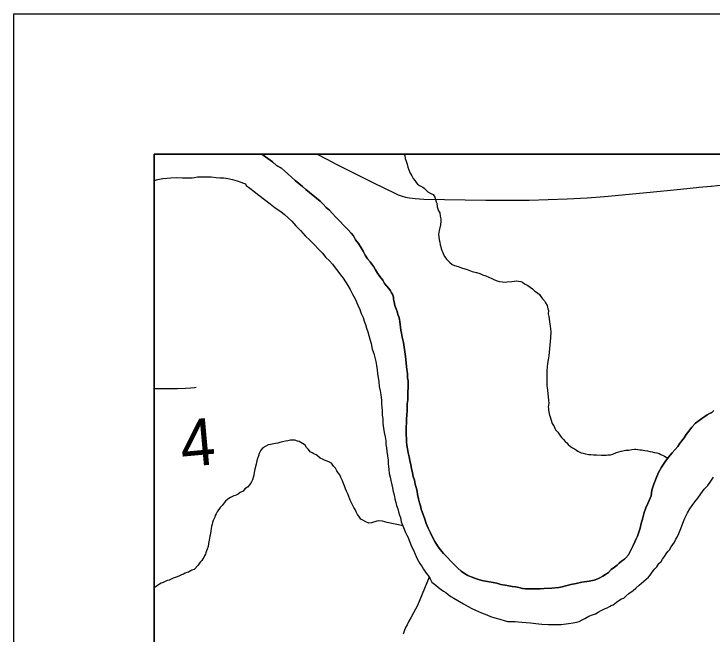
# Model space of a CAD drawing. Extents: x -483 to 680, y 0 to 440.
# Drawn here: x 37.11 to 79.41, y 366.86 to 404.45 of the extents above; entities that cross this region are included whole.
import ezdxf

# ---------------------------------------------------------------- set-up
doc = ezdxf.new("R2010")
doc.units = 0
for name, color, linetype in [('GM_X_Major_River', 7, 'Continuous'), ('GM_X_Minor_River', 7, 'Continuous'), ('GM_X_Township_Road', 7, 'Continuous'), ('GM_X_Township_Road_Text', 7, 'Continuous'), ('SH_Cut_Line', 7, 'Continuous'), ('SH_Text', 7, 'Continuous')]:
    doc.layers.add(name, color=color, linetype=linetype)

msp = doc.modelspace()

# ---------------------------------------------------------------- linework, layer by layer
at = {"layer": 'GM_X_Major_River'}
for points in [[(60.949, 382.647), (60.918, 382.895), (60.823, 383.676), (60.792, 383.962), (60.742, 384.248), (60.712, 384.534), (60.625, 384.859), (60.593, 385.106), (60.559, 385.278), (60.526, 385.469), (60.511, 385.64), (60.496, 385.792), (60.462, 385.945), (60.428, 386.098), (60.374, 386.232), (60.322, 386.404), (60.269, 386.577), (60.179, 386.769), (60.147, 386.998), (60.113, 387.169), (60.097, 387.284), (60.044, 387.456), (59.989, 387.552), (59.916, 387.668), (59.825, 387.803), (59.695, 387.94), (59.567, 388.114), (59.457, 388.306), (59.273, 388.539), (59.145, 388.732), (59.018, 388.944), (58.908, 389.118), (58.798, 389.273), (58.688, 389.427), (58.54, 389.602), (58.394, 389.834), (58.267, 390.065), (58.139, 390.277), (57.975, 390.528), (57.809, 390.76), (57.683, 391.01), (57.535, 391.166), (57.331, 391.38), (57.09, 391.633), (56.85, 391.886), (56.609, 392.139), (56.387, 392.372), (56.221, 392.566), (56.035, 392.723), (55.85, 392.917), (55.665, 393.093), (55.013, 393.622), (54.79, 393.799), (54.586, 393.994), (54.362, 394.171), (54.138, 394.347), (53.916, 394.562), (53.712, 394.757), (53.507, 394.933), (53.322, 395.109), (53.022, 395.268), (52.78, 395.483), (52.481, 395.681), (52.202, 395.897), (52.129, 395.95)], [(52.129, 395.95), (52.202, 395.897), (52.481, 395.681), (52.78, 395.483), (53.022, 395.268), (53.322, 395.109), (53.507, 394.933), (53.712, 394.757), (53.916, 394.562), (54.138, 394.347), (54.362, 394.171), (54.586, 393.994), (54.79, 393.799), (55.013, 393.622), (55.665, 393.093), (55.85, 392.917), (56.035, 392.723), (56.221, 392.566), (56.387, 392.372), (56.609, 392.139), (56.85, 391.886), (57.09, 391.633), (57.331, 391.38), (57.535, 391.166), (57.683, 391.01), (57.809, 390.76), (57.975, 390.528), (58.139, 390.277), (58.267, 390.065), (58.394, 389.834), (58.54, 389.602), (58.688, 389.427), (58.798, 389.273), (58.908, 389.118), (59.018, 388.944), (59.145, 388.732), (59.273, 388.539), (59.457, 388.306), (59.567, 388.114), (59.695, 387.94), (59.825, 387.803), (59.916, 387.668), (59.989, 387.552), (60.044, 387.456), (60.097, 387.284), (60.113, 387.169), (60.147, 386.998), (60.179, 386.769), (60.269, 386.577), (60.322, 386.404), (60.374, 386.232), (60.428, 386.098), (60.462, 385.945), (60.496, 385.792), (60.511, 385.64), (60.526, 385.469), (60.559, 385.278), (60.593, 385.106), (60.625, 384.859), (60.712, 384.534), (60.742, 384.248), (60.792, 383.962), (60.823, 383.676), (60.918, 382.895), (60.949, 382.647)], [(45.608, 394.363), (45.821, 394.406), (46.126, 394.475), (46.621, 394.519), (46.983, 394.529), (47.324, 394.52)], [(45.608, 394.363), (45.821, 394.406), (46.126, 394.475), (46.621, 394.519), (46.983, 394.529), (47.324, 394.52)], [(47.324, 394.52), (47.571, 394.514), (47.742, 394.51), (47.913, 394.524), (48.046, 394.54), (48.237, 394.573), (48.503, 394.585), (48.807, 394.578), (49.054, 394.571), (49.357, 394.545), (49.603, 394.519), (49.831, 394.513), (50.077, 394.469), (50.36, 394.405), (50.625, 394.342), (50.85, 394.26), (51.02, 394.199), (51.133, 394.158), (51.187, 394.042), (51.392, 393.885), (51.653, 393.689), (51.951, 393.472), (52.286, 393.198), (52.641, 392.942), (52.939, 392.707), (53.275, 392.47), (53.498, 392.294), (53.721, 392.098), (53.944, 391.883), (54.184, 391.612), (54.462, 391.32), (54.758, 391.008), (55.054, 390.716), (55.795, 389.957), (55.997, 389.686), (56.22, 389.49), (56.405, 389.276), (56.57, 389.063), (56.736, 388.85), (56.902, 388.637), (57.048, 388.425), (57.195, 388.212), (57.341, 387.98), (57.487, 387.749), (57.613, 387.461), (57.777, 387.172), (57.938, 386.807), (58.065, 386.538), (58.153, 386.289), (58.262, 386.058), (58.332, 385.828), (58.402, 385.618), (58.473, 385.407), (58.543, 385.177), (58.614, 384.967), (58.665, 384.737), (58.754, 384.469), (58.821, 384.126), (58.91, 383.877), (58.979, 383.628), (59.03, 383.38), (59.081, 383.132), (59.113, 382.884), (59.145, 382.636), (59.177, 382.408), (59.208, 382.141), (59.24, 381.874), (59.29, 381.607), (59.341, 381.359), (59.37, 381.035), (59.384, 380.826), (59.398, 380.617), (59.411, 380.389), (59.424, 380.142), (59.456, 379.894), (59.468, 379.628), (59.499, 379.342), (59.549, 379.075), (59.6, 378.808), (59.632, 378.579), (59.645, 378.351), (59.678, 378.141), (59.692, 377.932), (59.773, 377.398), (59.787, 377.189), (59.802, 377.018), (59.816, 376.827), (59.848, 376.599), (59.9, 376.369), (59.952, 376.178), (60.002, 375.911), (60.054, 375.72), (60.087, 375.51), (60.139, 375.3), (60.19, 375.052), (60.241, 374.842), (60.293, 374.65), (60.365, 374.459), (60.417, 374.267), (60.469, 374.076), (60.522, 373.923)], [(47.324, 394.52), (47.571, 394.514), (47.742, 394.51), (47.913, 394.524), (48.046, 394.54), (48.237, 394.573), (48.503, 394.585), (48.807, 394.578), (49.054, 394.571), (49.357, 394.545), (49.603, 394.519), (49.831, 394.513), (50.077, 394.469), (50.36, 394.405), (50.625, 394.342), (50.85, 394.26), (51.02, 394.199), (51.133, 394.158), (51.187, 394.042), (51.392, 393.885), (51.653, 393.689), (51.951, 393.472), (52.286, 393.198), (52.641, 392.942), (52.939, 392.707), (53.275, 392.47), (53.498, 392.294), (53.721, 392.098), (53.944, 391.883), (54.184, 391.612), (54.462, 391.32), (54.758, 391.008), (55.054, 390.716), (55.795, 389.957), (55.997, 389.686), (56.22, 389.49), (56.405, 389.276), (56.57, 389.063), (56.736, 388.85), (56.902, 388.637), (57.048, 388.425), (57.195, 388.212), (57.341, 387.98), (57.487, 387.749), (57.613, 387.461), (57.777, 387.172), (57.938, 386.807), (58.065, 386.538), (58.153, 386.289), (58.262, 386.058), (58.332, 385.828), (58.402, 385.618), (58.473, 385.407), (58.543, 385.177), (58.614, 384.967), (58.665, 384.737), (58.754, 384.469), (58.821, 384.126), (58.91, 383.877), (58.979, 383.628), (59.03, 383.38), (59.081, 383.132), (59.113, 382.884), (59.145, 382.636), (59.177, 382.408), (59.208, 382.141), (59.24, 381.874), (59.29, 381.607), (59.341, 381.359), (59.37, 381.035), (59.384, 380.826), (59.398, 380.617), (59.411, 380.389), (59.424, 380.142), (59.456, 379.894), (59.468, 379.628), (59.499, 379.342), (59.549, 379.075), (59.6, 378.808), (59.632, 378.579), (59.645, 378.351), (59.678, 378.141), (59.692, 377.932), (59.773, 377.398), (59.787, 377.189), (59.802, 377.018), (59.816, 376.827), (59.848, 376.599), (59.9, 376.369), (59.952, 376.178), (60.002, 375.911), (60.054, 375.72), (60.087, 375.51), (60.139, 375.3), (60.19, 375.052), (60.241, 374.842), (60.293, 374.65), (60.365, 374.459), (60.417, 374.267), (60.469, 374.076), (60.522, 373.923)], [(74.973, 373.043), (74.891, 372.798), (74.811, 372.629), (74.73, 372.442), (74.63, 372.235), (74.55, 372.066), (74.35, 371.673), (74.193, 371.487), (74.096, 371.394), (73.922, 371.285), (73.786, 371.155), (73.651, 371.045), (73.495, 370.916), (73.302, 370.769), (73.127, 370.602), (72.952, 370.474), (72.798, 370.364), (72.644, 370.292), (72.49, 370.201), (72.26, 370.131), (71.955, 370.062), (71.516, 369.998), (71.173, 369.93), (70.848, 369.863), (70.332, 369.724), (70.122, 369.691), (69.703, 369.645), (69.227, 369.619), (68.999, 369.606), (68.714, 369.594), (68.505, 369.599), (68.296, 369.605), (68.107, 369.609), (67.917, 369.633), (67.709, 369.676), (67.502, 369.72), (67.293, 369.744), (67.085, 369.787), (66.878, 369.831), (66.613, 369.875), (66.367, 369.938), (66.027, 370.004), (65.8, 370.048), (65.555, 370.092), (65.309, 370.155), (65.064, 370.237), (64.82, 370.339), (64.613, 370.42), (64.407, 370.539), (64.202, 370.677), (63.997, 370.853), (63.793, 371.048), (63.127, 371.749), (62.943, 371.981), (62.778, 372.213), (62.613, 372.465), (62.468, 372.734), (62.342, 373.003), (62.215, 373.272), (62.09, 373.56), (62.001, 373.828), (61.931, 374.039), (61.841, 374.269), (61.789, 374.441), (61.736, 374.633), (61.684, 374.824), (61.614, 375.054), (61.564, 375.321), (61.531, 375.53), (61.479, 375.741), (61.428, 375.951), (61.376, 376.18), (61.306, 376.41), (61.255, 376.639), (61.205, 376.906), (61.153, 377.116), (61.102, 377.383), (61.051, 377.613), (61, 377.842), (60.949, 378.09), (60.917, 378.319), (60.903, 378.509), (60.889, 378.718), (60.875, 378.927), (60.88, 379.117), (60.869, 379.421), (60.894, 379.667), (60.899, 379.895), (60.906, 380.142), (60.931, 380.388), (60.936, 380.616), (60.942, 380.825), (60.966, 381.052), (60.971, 381.223), (60.975, 381.413), (60.98, 381.583), (61.003, 381.773), (60.99, 382.001), (60.995, 382.21), (60.962, 382.4), (60.949, 382.647)], [(60.949, 382.647), (60.962, 382.4), (60.995, 382.21), (60.99, 382.001), (61.003, 381.773), (60.98, 381.583), (60.975, 381.413), (60.971, 381.223), (60.966, 381.052), (60.942, 380.825), (60.936, 380.616), (60.931, 380.388), (60.906, 380.142), (60.899, 379.895), (60.894, 379.667), (60.869, 379.421), (60.88, 379.117), (60.875, 378.927), (60.889, 378.718), (60.903, 378.509), (60.917, 378.319), (60.949, 378.09), (61, 377.842), (61.051, 377.613), (61.102, 377.383), (61.153, 377.116), (61.205, 376.906), (61.255, 376.639), (61.306, 376.41), (61.376, 376.18), (61.428, 375.951), (61.479, 375.741), (61.531, 375.53), (61.564, 375.321), (61.614, 375.054), (61.684, 374.824), (61.736, 374.633), (61.789, 374.441), (61.841, 374.269), (61.931, 374.039), (62.001, 373.828), (62.09, 373.56), (62.215, 373.272), (62.342, 373.003), (62.468, 372.734), (62.613, 372.465), (62.778, 372.213), (62.943, 371.981), (63.127, 371.749), (63.793, 371.048), (63.997, 370.853), (64.202, 370.677), (64.407, 370.539), (64.613, 370.42), (64.82, 370.339), (65.064, 370.237), (65.309, 370.155), (65.555, 370.092), (65.8, 370.048), (66.027, 370.004), (66.367, 369.938), (66.613, 369.875), (66.878, 369.831), (67.085, 369.787), (67.293, 369.744), (67.502, 369.72), (67.709, 369.676), (67.917, 369.633), (68.107, 369.609), (68.296, 369.605), (68.505, 369.599), (68.714, 369.594), (68.999, 369.606), (69.227, 369.619), (69.703, 369.645), (70.122, 369.691), (70.332, 369.724), (70.848, 369.863), (71.173, 369.93), (71.516, 369.998), (71.955, 370.062), (72.26, 370.131), (72.49, 370.201), (72.644, 370.292), (72.798, 370.364), (72.952, 370.474), (73.127, 370.602), (73.302, 370.769), (73.495, 370.916), (73.651, 371.045), (73.786, 371.155), (73.922, 371.285), (74.096, 371.394), (74.193, 371.487), (74.35, 371.673), (74.55, 372.066), (74.63, 372.235), (74.73, 372.442), (74.811, 372.629), (74.891, 372.798), (74.973, 373.043)], [(79.507, 380.41), (79.39, 380.299), (79.255, 380.226), (79.102, 380.154), (78.966, 380.044), (78.792, 379.934), (78.618, 379.806), (78.405, 379.64), (78.19, 379.399), (77.994, 379.157), (77.837, 378.952), (77.718, 378.765), (77.561, 378.56), (77.443, 378.392), (77.325, 378.224), (77.168, 378.039), (76.993, 377.853), (76.777, 377.593), (76.541, 377.276), (76.344, 376.977), (76.165, 376.659), (76.024, 376.321), (75.881, 375.944), (75.758, 375.587), (75.712, 375.246), (75.651, 375.096), (75.591, 374.964), (75.51, 374.776), (75.39, 374.514), (75.288, 374.231), (75.204, 373.911), (75.119, 373.571), (75.055, 373.288), (74.973, 373.043)], [(74.973, 373.043), (75.055, 373.288), (75.119, 373.571), (75.204, 373.911), (75.288, 374.231), (75.39, 374.514), (75.51, 374.776), (75.591, 374.964), (75.651, 375.096), (75.712, 375.246), (75.758, 375.587), (75.881, 375.944), (76.024, 376.321), (76.165, 376.659), (76.344, 376.977), (76.541, 377.276), (76.777, 377.593), (76.993, 377.853), (77.168, 378.039), (77.325, 378.224), (77.443, 378.392), (77.561, 378.56), (77.718, 378.765), (77.837, 378.952), (77.994, 379.157), (78.19, 379.399), (78.405, 379.64), (78.618, 379.806), (78.792, 379.934), (78.966, 380.044), (79.102, 380.154), (79.255, 380.226), (79.39, 380.299), (79.507, 380.41)], [(77.646, 373.583), (77.767, 373.884), (77.927, 374.202), (78.066, 374.446), (78.204, 374.651), (78.362, 374.875), (78.538, 375.098), (78.735, 375.359), (78.932, 375.639), (79.146, 375.861), (79.324, 376.123), (79.501, 376.365)], [(77.646, 373.583), (77.767, 373.884), (77.927, 374.202), (78.066, 374.446), (78.204, 374.651), (78.362, 374.875), (78.538, 375.098), (78.735, 375.359), (78.932, 375.639), (79.146, 375.861), (79.324, 376.123), (79.501, 376.365)], [(60.522, 373.923), (60.572, 373.656), (60.681, 373.425), (60.751, 373.214), (60.842, 373.022), (60.913, 372.85), (60.986, 372.715), (61.04, 372.599), (61.111, 372.389), (61.2, 372.159), (61.308, 371.947), (61.416, 371.697), (61.542, 371.428), (61.706, 371.139), (61.834, 370.946), (61.925, 370.792), (61.998, 370.676), (62.09, 370.56), (62.201, 370.405), (62.329, 370.212), (62.437, 370), (62.661, 369.824), (62.828, 369.687), (62.996, 369.568), (63.127, 369.47), (63.276, 369.371), (63.425, 369.254), (63.574, 369.136), (63.762, 369.036), (64.342, 368.699), (64.623, 368.54), (64.848, 368.42), (65.073, 368.319), (65.261, 368.238), (65.43, 368.158), (65.6, 368.097), (65.769, 368.017), (65.976, 367.935), (66.239, 367.853), (66.541, 367.769), (66.805, 367.686), (67.012, 367.624), (67.259, 367.618), (67.468, 367.613), (67.658, 367.608), (67.885, 367.583), (68.15, 367.557), (68.416, 367.532), (68.738, 367.504), (69.097, 367.457), (69.496, 367.447), (69.876, 367.438), (70.256, 367.447), (70.713, 367.492), (70.999, 367.542), (71.19, 367.575), (71.362, 367.628), (71.535, 367.718), (71.708, 367.809), (71.939, 367.936), (72.17, 368.025), (72.342, 368.097), (72.497, 368.188), (72.689, 368.297), (72.881, 368.387), (73.054, 368.458), (73.189, 368.531), (73.304, 368.585), (73.419, 368.639), (73.516, 368.712), (73.613, 368.786), (73.749, 368.896), (73.922, 368.987), (74.056, 369.04), (74.192, 369.151), (74.367, 369.317), (74.619, 369.501), (74.793, 369.648), (74.988, 369.833), (75.551, 370.313), (75.648, 370.424), (75.747, 370.555), (75.845, 370.685), (75.943, 370.816), (76.06, 370.945), (76.179, 371.132), (76.315, 371.262), (76.414, 371.411), (76.531, 371.56), (76.631, 371.729), (76.729, 371.859), (76.827, 371.97), (76.926, 372.139), (77.025, 372.288), (77.123, 372.438), (77.222, 372.606), (77.302, 372.737), (77.402, 372.962), (77.483, 373.169), (77.564, 373.357), (77.646, 373.583)], [(60.522, 373.923), (60.572, 373.656), (60.681, 373.425), (60.751, 373.214), (60.842, 373.022), (60.913, 372.85), (60.986, 372.715), (61.04, 372.599), (61.111, 372.389), (61.2, 372.159), (61.308, 371.947), (61.416, 371.697), (61.542, 371.428), (61.706, 371.139), (61.834, 370.946), (61.925, 370.792), (61.998, 370.676), (62.09, 370.56), (62.201, 370.405), (62.329, 370.212), (62.437, 370), (62.661, 369.824), (62.828, 369.687), (62.996, 369.568), (63.127, 369.47), (63.276, 369.371), (63.425, 369.254), (63.574, 369.136), (63.762, 369.036), (64.342, 368.699), (64.623, 368.54), (64.848, 368.42), (65.073, 368.319), (65.261, 368.238), (65.43, 368.158), (65.6, 368.097), (65.769, 368.017), (65.976, 367.935), (66.239, 367.853), (66.541, 367.769), (66.805, 367.686), (67.012, 367.624), (67.259, 367.618), (67.468, 367.613), (67.658, 367.608), (67.885, 367.583), (68.15, 367.557), (68.416, 367.532), (68.738, 367.504), (69.097, 367.457), (69.496, 367.447), (69.876, 367.438), (70.256, 367.447), (70.713, 367.492), (70.999, 367.542), (71.19, 367.575), (71.362, 367.628), (71.535, 367.718), (71.708, 367.809), (71.939, 367.936), (72.17, 368.025), (72.342, 368.097), (72.497, 368.188), (72.689, 368.297), (72.881, 368.387), (73.054, 368.458), (73.189, 368.531), (73.304, 368.585), (73.419, 368.639), (73.516, 368.712), (73.613, 368.786), (73.749, 368.896), (73.922, 368.987), (74.056, 369.04), (74.192, 369.151), (74.367, 369.317), (74.619, 369.501), (74.793, 369.648), (74.988, 369.833), (75.551, 370.313), (75.648, 370.424), (75.747, 370.555), (75.845, 370.685), (75.943, 370.816), (76.06, 370.945), (76.179, 371.132), (76.315, 371.262), (76.414, 371.411), (76.531, 371.56), (76.631, 371.729), (76.729, 371.859), (76.827, 371.97), (76.926, 372.139), (77.025, 372.288), (77.123, 372.438), (77.222, 372.606), (77.302, 372.737), (77.402, 372.962), (77.483, 373.169), (77.564, 373.357), (77.646, 373.583)]]:
    msp.add_lwpolyline(points, dxfattribs=at)
at = {"layer": 'GM_X_Minor_River'}
for points in [[(60.76, 395.95), (60.786, 395.849), (60.82, 395.697), (60.873, 395.524), (60.925, 395.352), (60.978, 395.161), (61.031, 395.008), (61.12, 394.797), (61.211, 394.642), (61.302, 394.469), (61.413, 394.333), (61.486, 394.237), (61.56, 394.14), (61.671, 394.042), (61.765, 394.002), (61.878, 393.942)], [(61.878, 393.942), (61.971, 393.883), (62.064, 393.785), (62.194, 393.668), (62.362, 393.569), (62.513, 393.508), (62.603, 393.335), (62.657, 393.2), (62.692, 393.067), (62.727, 392.971), (62.76, 392.761), (62.83, 392.512), (62.903, 392.397), (62.935, 392.187), (62.97, 392.034), (62.966, 391.882), (62.961, 391.674), (62.918, 391.485), (62.876, 391.315), (62.854, 391.202), (62.832, 391.088), (62.847, 390.936), (62.881, 390.764), (62.915, 390.611), (62.93, 390.459), (62.965, 390.325), (63, 390.229), (63.035, 390.115), (63.089, 389.98), (63.143, 389.865), (63.216, 389.73), (63.326, 389.594), (63.4, 389.498), (63.511, 389.381), (63.66, 389.263), (63.81, 389.202), (64.018, 389.14), (64.225, 389.059), (64.564, 388.955), (64.865, 388.834), (65.129, 388.77), (65.336, 388.708), (65.506, 388.646), (65.694, 388.585), (65.882, 388.485), (66.07, 388.404), (66.22, 388.324), (66.389, 388.263), (66.521, 388.241), (66.711, 388.217), (66.862, 388.194), (66.995, 388.21), (67.281, 388.241), (67.415, 388.256), (67.548, 388.272), (67.68, 388.249), (67.813, 388.227), (67.926, 388.186), (68.037, 388.088), (68.243, 387.988), (68.393, 387.89), (68.523, 387.791), (68.672, 387.654), (68.821, 387.537), (68.951, 387.438), (69.025, 387.323), (69.135, 387.187), (69.246, 387.051), (69.319, 386.935), (69.41, 386.781), (69.445, 386.685), (69.462, 386.571), (69.497, 386.475), (69.473, 386.267), (69.526, 386.114), (69.541, 385.961), (69.556, 385.79), (69.606, 385.523), (69.636, 385.199), (69.627, 384.82), (69.523, 383.721), (69.479, 383.494), (69.436, 383.267), (69.412, 383.059), (69.406, 382.812), (69.399, 382.566), (69.394, 382.357), (69.389, 382.148), (69.402, 381.92), (69.433, 381.653), (69.466, 381.425), (69.48, 381.234), (69.494, 381.025), (69.508, 380.854), (69.505, 380.721), (69.484, 380.627), (69.5, 380.531), (69.498, 380.436), (69.514, 380.322), (69.531, 380.227), (69.566, 380.131)], [(69.566, 380.131), (69.602, 380.035), (69.636, 379.882), (69.725, 379.633), (69.834, 379.44), (69.924, 379.248), (70.053, 379.093), (70.145, 378.977), (70.218, 378.861), (70.311, 378.764), (70.403, 378.647), (70.514, 378.531), (70.607, 378.452), (70.699, 378.355), (70.829, 378.238), (70.942, 378.159), (71.072, 378.08), (71.184, 378.001), (71.278, 377.942), (71.39, 377.882), (71.484, 377.841), (71.598, 377.819), (71.749, 377.778), (71.919, 377.754), (72.071, 377.75), (72.222, 377.728), (72.412, 377.723), (72.715, 377.696), (72.868, 377.711), (73.001, 377.708), (73.096, 377.724), (73.248, 377.72), (73.401, 377.774), (73.612, 377.863), (73.899, 377.951), (74.185, 378.001), (74.357, 378.015), (74.547, 378.048), (74.7, 378.063), (74.795, 378.061), (74.908, 378.039), (75.022, 378.036), (75.136, 378.033), (75.23, 378.012), (75.344, 377.99), (75.495, 377.967), (75.646, 377.925), (75.778, 377.903), (75.929, 377.861), (76.062, 377.839), (76.213, 377.797), (76.306, 377.738), (76.438, 377.677), (76.531, 377.637), (76.728, 377.526)], [(60.682, 373.421), (59.717, 373.62), (59.434, 373.704), (59.207, 373.728), (59.092, 373.712), (58.767, 373.607), (58.615, 373.592), (58.427, 373.672), (58.239, 373.772), (58.127, 373.832), (57.998, 374.006), (57.925, 374.103), (57.834, 374.276), (57.78, 374.41), (57.707, 374.526), (57.617, 374.699), (57.563, 374.815), (57.508, 374.93), (57.454, 375.045), (57.401, 375.199), (57.329, 375.371), (57.257, 375.525), (57.204, 375.659), (57.15, 375.794), (57.079, 375.985), (57.007, 376.158), (56.917, 376.35), (56.845, 376.504), (56.753, 376.639), (56.68, 376.755), (56.589, 376.909), (56.479, 377.045), (56.35, 377.219), (56.219, 377.279), (56.087, 377.34), (55.955, 377.381), (55.843, 377.441), (55.655, 377.522), (55.506, 377.658), (55.413, 377.718), (55.281, 377.778), (55.169, 377.838), (55.057, 377.917), (54.946, 378.052), (54.835, 378.169), (54.744, 378.304), (54.594, 378.403), (54.482, 378.482), (54.389, 378.541), (54.294, 378.563), (54.125, 378.605), (53.992, 378.608), (53.859, 378.612), (53.706, 378.578), (53.553, 378.544), (53.381, 378.51), (53.21, 378.476), (53.095, 378.441), (52.961, 378.407), (52.847, 378.39), (52.751, 378.374), (52.656, 378.357), (52.503, 378.323), (52.368, 378.251), (52.195, 378.141), (52.058, 378.012), (51.958, 377.805), (51.917, 377.674), (51.856, 377.504), (51.833, 377.353), (51.79, 377.164), (51.707, 376.862), (51.664, 376.654), (51.641, 376.503), (51.557, 376.201), (51.497, 376.089), (51.398, 375.92), (51.262, 375.772), (51.107, 375.662), (50.99, 375.532), (50.817, 375.442), (50.7, 375.349), (50.565, 375.277), (50.432, 375.242), (50.316, 375.188), (50.22, 375.134), (50.066, 375.043), (49.93, 374.913), (49.851, 374.82), (49.714, 374.653), (49.597, 374.542), (49.42, 374.261), (49.36, 374.149), (49.3, 374.056), (49.279, 373.942), (49.178, 373.736), (49.138, 373.623), (49.116, 373.51), (49.075, 373.397), (49.052, 373.245), (49.03, 373.113)], [(49.03, 373.113), (49.007, 372.943), (48.984, 372.791), (48.962, 372.678), (48.94, 372.546), (48.897, 372.357), (48.873, 372.167), (48.812, 371.998), (48.772, 371.904), (48.731, 371.791), (48.71, 371.697), (48.65, 371.603), (48.61, 371.509), (48.551, 371.416), (48.491, 371.323), (48.413, 371.23), (48.335, 371.137), (48.275, 371.043), (48.022, 370.784), (47.888, 370.73), (47.791, 370.676), (47.676, 370.622), (47.58, 370.586), (47.484, 370.551), (47.388, 370.496), (47.254, 370.442), (47.138, 370.388), (47.004, 370.335), (46.87, 370.281), (46.755, 370.246), (46.601, 370.174), (46.506, 370.138), (46.391, 370.103), (46.275, 370.049), (46.141, 369.996), (46.026, 369.942), (45.929, 369.887), (45.814, 369.814), (45.717, 369.741), (45.608, 369.672)], [(62.261, 370.314), (61.567, 368.598), (61.447, 368.373), (61.308, 368.149), (61.169, 367.887), (61.03, 367.643), (60.929, 367.418), (60.83, 367.249), (60.749, 367.043), (60.687, 366.854)]]:
    msp.add_lwpolyline(points, dxfattribs=at)
at = {"layer": 'GM_X_Township_Road'}
for points in [[(55.475, 395.95), (56.073, 395.646), (56.679, 395.33), (58.844, 394.237), (60.225, 393.559), (60.394, 393.482), (60.567, 393.416), (60.835, 393.342), (61.079, 393.296), (61.416, 393.257), (61.94, 393.213), (65.696, 393.163), (68.332, 393.156), (70.631, 393.241), (71.842, 393.301), (72.898, 393.375), (75.651, 393.649), (77.291, 393.808), (78.462, 393.937), (78.599, 393.95)], [(79.373, 394.021), (80.406, 394.134), (81.517, 394.27), (82.874, 394.441), (84.045, 394.599), (85.153, 394.742), (87.687, 395.008), (90.653, 395.333), (91.982, 395.474), (92.477, 395.532), (95.581, 395.95)], [(78.599, 393.95), (79.324, 394.016), (79.373, 394.021)], [(45.608, 381.754), (47.027, 381.755), (47.493, 381.76), (47.834, 381.784), (48.049, 381.816), (48.14, 381.837)]]:
    msp.add_lwpolyline(points, dxfattribs=at)
at = {"layer": 'SH_Cut_Line'}
msp.add_lwpolyline([(385.608, 55.95), (385.608, 395.95), (45.608, 395.95), (45.608, 281.486), (47.873, 281.454), (57.759, 281.293), (64.783, 281.226), (67.114, 281.188), (73.333, 281.086), (75.975, 281.043), (77.151, 281.034), (77.105, 279.466), (77.065, 275.738), (77.043, 273.874), (76.996, 269.37), (76.941, 265.642), (76.868, 261.138), (76.791, 256.013), (76.689, 249.801), (76.636, 246.539)], dxfattribs=at)
at = {"layer": 'SH_Text'}
for points in [[(37.108, 404.45), (394.108, 404.45), (394.108, 47.45), (37.108, 47.45)], [(45.608, 395.95), (385.608, 395.95), (385.608, 55.95), (45.608, 55.95)]]:
    msp.add_lwpolyline(points, close=True, dxfattribs=at)

# ---------------------------------------------------------------- texts
at = {"layer": 'GM_X_Township_Road_Text'}
msp.add_text('4', height=2.841, rotation=5.1863, dxfattribs=at).set_placement((47.304, 376.971))

doc.saveas('drawing.dxf')
